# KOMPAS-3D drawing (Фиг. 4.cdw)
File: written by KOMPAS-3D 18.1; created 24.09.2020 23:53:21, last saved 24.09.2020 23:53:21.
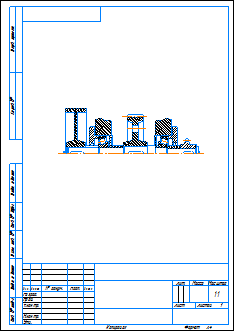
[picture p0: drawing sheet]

Sheet 1: A4, portrait

Document properties: Автор: user; Полное имя файла: C:\Users\user\Desktop\Задания\Фиг. 4.cdw

Title block, sheet 1: scale: 1:1; Количество листов документа: 1; Форматы листов документа: A4

Dimensions and other numbers on the sheet: 1:1; 1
